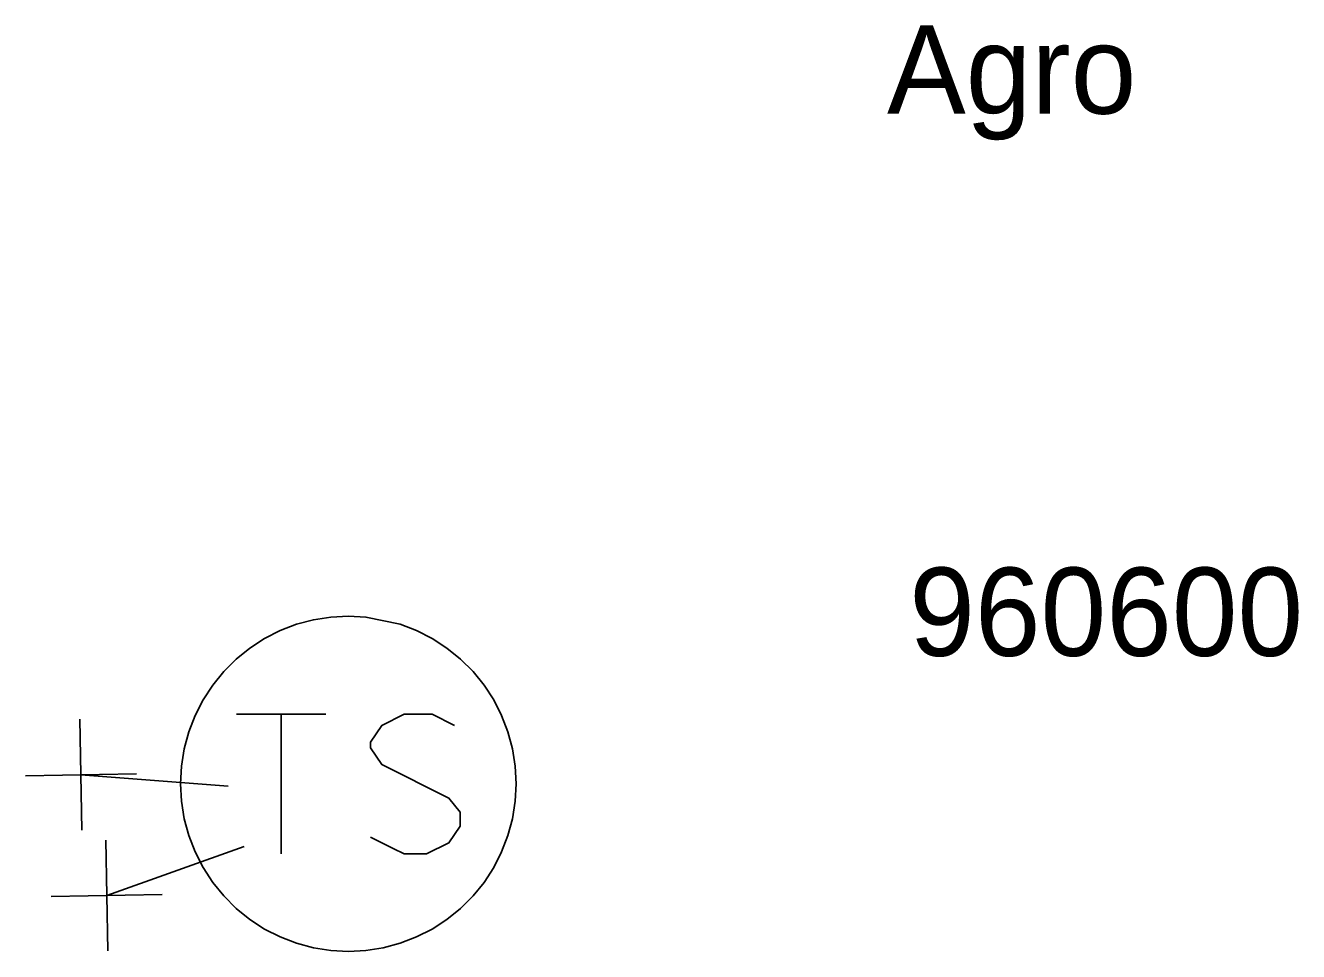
# Model space of a CAD drawing. Extents: x -762504 to -761250, y -1152974 to -1152253.
# Drawn here: x -762404.56 to -762390.22, y -1152349.97 to -1152339.54 of the extents above; entities that cross this region are included whole.
import ezdxf

# ---------------------------------------------------------------- set-up
doc = ezdxf.new("R2010")
doc.units = 0
for name, color, linetype in [('Vrstva 25', 7, 'Continuous'), ('Vrstva 26', 7, 'Continuous'), ('Vrstva 27', 7, 'Continuous'), ('Vrstva 34', 7, 'Continuous'), ('Vrstva 59', 7, 'Continuous')]:
    doc.layers.add(name, color=color, linetype=linetype)

msp = doc.modelspace()

# ---------------------------------------------------------------- linework, layer by layer
at = {"layer": 'Vrstva 25'}
for points in [[(-762399.027, -1152348.081), (-762399.038, -1152347.884), (-762399.069, -1152347.688), (-762399.12, -1152347.497), (-762399.192, -1152347.312), (-762399.281, -1152347.137), (-762399.389, -1152346.971), (-762399.513, -1152346.817), (-762399.653, -1152346.677), (-762399.807, -1152346.553), (-762399.973, -1152346.445), (-762400.149, -1152346.355), (-762400.333, -1152346.284), (-762400.72, -1152346.202), (-762400.72, -1152346.202), (-762400.917, -1152346.191), (-762401.115, -1152346.202), (-762401.311, -1152346.233), (-762401.501, -1152346.284), (-762401.687, -1152346.355), (-762401.862, -1152346.445), (-762402.028, -1152346.553), (-762402.182, -1152346.677), (-762402.322, -1152346.817), (-762402.446, -1152346.971), (-762402.554, -1152347.137), (-762402.644, -1152347.312), (-762402.715, -1152347.497), (-762402.766, -1152347.688), (-762402.797, -1152347.884), (-762402.808, -1152348.081), (-762402.797, -1152348.279), (-762402.766, -1152348.475), (-762402.715, -1152348.665), (-762402.644, -1152348.85), (-762402.554, -1152349.026), (-762402.446, -1152349.192), (-762402.321, -1152349.346), (-762402.182, -1152349.485), (-762402.028, -1152349.61), (-762401.862, -1152349.718), (-762401.686, -1152349.808), (-762401.501, -1152349.879), (-762401.311, -1152349.93), (-762401.115, -1152349.961), (-762400.917, -1152349.972), (-762400.72, -1152349.961), (-762400.525, -1152349.93), (-762400.333, -1152349.879), (-762400.149, -1152349.808), (-762399.973, -1152349.718), (-762399.807, -1152349.61), (-762399.653, -1152349.485), (-762399.513, -1152349.346), (-762399.389, -1152349.192), (-762399.281, -1152349.026), (-762399.192, -1152348.85), (-762399.12, -1152348.665), (-762399.069, -1152348.475), (-762399.038, -1152348.279), (-762399.027, -1152348.081)], [(-762402.179, -1152347.298), (-762401.171, -1152347.298)], [(-762401.675, -1152347.298), (-762401.675, -1152348.872)], [(-762399.722, -1152347.424), (-762399.974, -1152347.298), (-762400.289, -1152347.298), (-762400.541, -1152347.424), (-762400.667, -1152347.612), (-762400.667, -1152347.676), (-762400.541, -1152347.864), (-762399.785, -1152348.242), (-762399.659, -1152348.4), (-762399.659, -1152348.558), (-762399.785, -1152348.746), (-762400.037, -1152348.872), (-762400.289, -1152348.872), (-762400.415, -1152348.81), (-762400.667, -1152348.684)]]:
    msp.add_lwpolyline(points, dxfattribs=at)
at = {"layer": 'Vrstva 34'}
for points in [[(-762403.919, -1152348.605), (-762403.941, -1152347.355)], [(-762404.555, -1152347.991), (-762403.305, -1152347.969)], [(-762403.629, -1152349.965), (-762403.651, -1152348.715)], [(-762404.265, -1152349.351), (-762403.015, -1152349.329)]]:
    msp.add_lwpolyline(points, dxfattribs=at)
at = {"layer": 'Vrstva 59'}
for points in [[(-762402.27, -1152348.11), (-762403.93, -1152347.98)], [(-762402.09, -1152348.79), (-762403.64, -1152349.34)]]:
    msp.add_lwpolyline(points, dxfattribs=at)

# ---------------------------------------------------------------- texts
at = {"layer": 'Vrstva 26'}
msp.add_text('960600', height=0.9943, dxfattribs=at).set_placement((-762394.6, -1152346.64))
at = {"layer": 'Vrstva 27'}
msp.add_text('Agro', height=0.9943, dxfattribs=at).set_placement((-762394.85, -1152340.53))

doc.saveas('drawing.dxf')
